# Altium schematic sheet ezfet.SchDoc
size 431 x 279 mm; Date: Not shown in title block; ApprovedBy: Not shown in title block; CheckedBy: Not shown in title block; Author: Not shown in title block; CompanyName: Not shown in title block; Engineer: Not shown in title block; Organization: Not shown in title block; Address1: Not shown in title block; Address2: Not shown in title block; Address3: Not shown in title block; Address4: Not shown in title block; DocumentNumber: 1; Revision: Use project parameter SCH_Rev; SheetNumber: 1; SheetTotal: 6; PageSetup: Record=PageOptions¦CenterHorizontal=True¦CenterVertical=True¦PrintScale=1.00¦XCorrection=1.00¦YCorrection=1.00¦PrintKind=0¦BorderSize=5000000¦LeftOffset=0¦BottomOffset=0¦Orientation=2¦PaperLength=1000¦PaperWidth=1000¦Scale=100¦PaperSource=15¦PrintQuality=600¦MediaType=1¦DitherType=10¦PaperKind=Letter¦PrintScaleMode=1
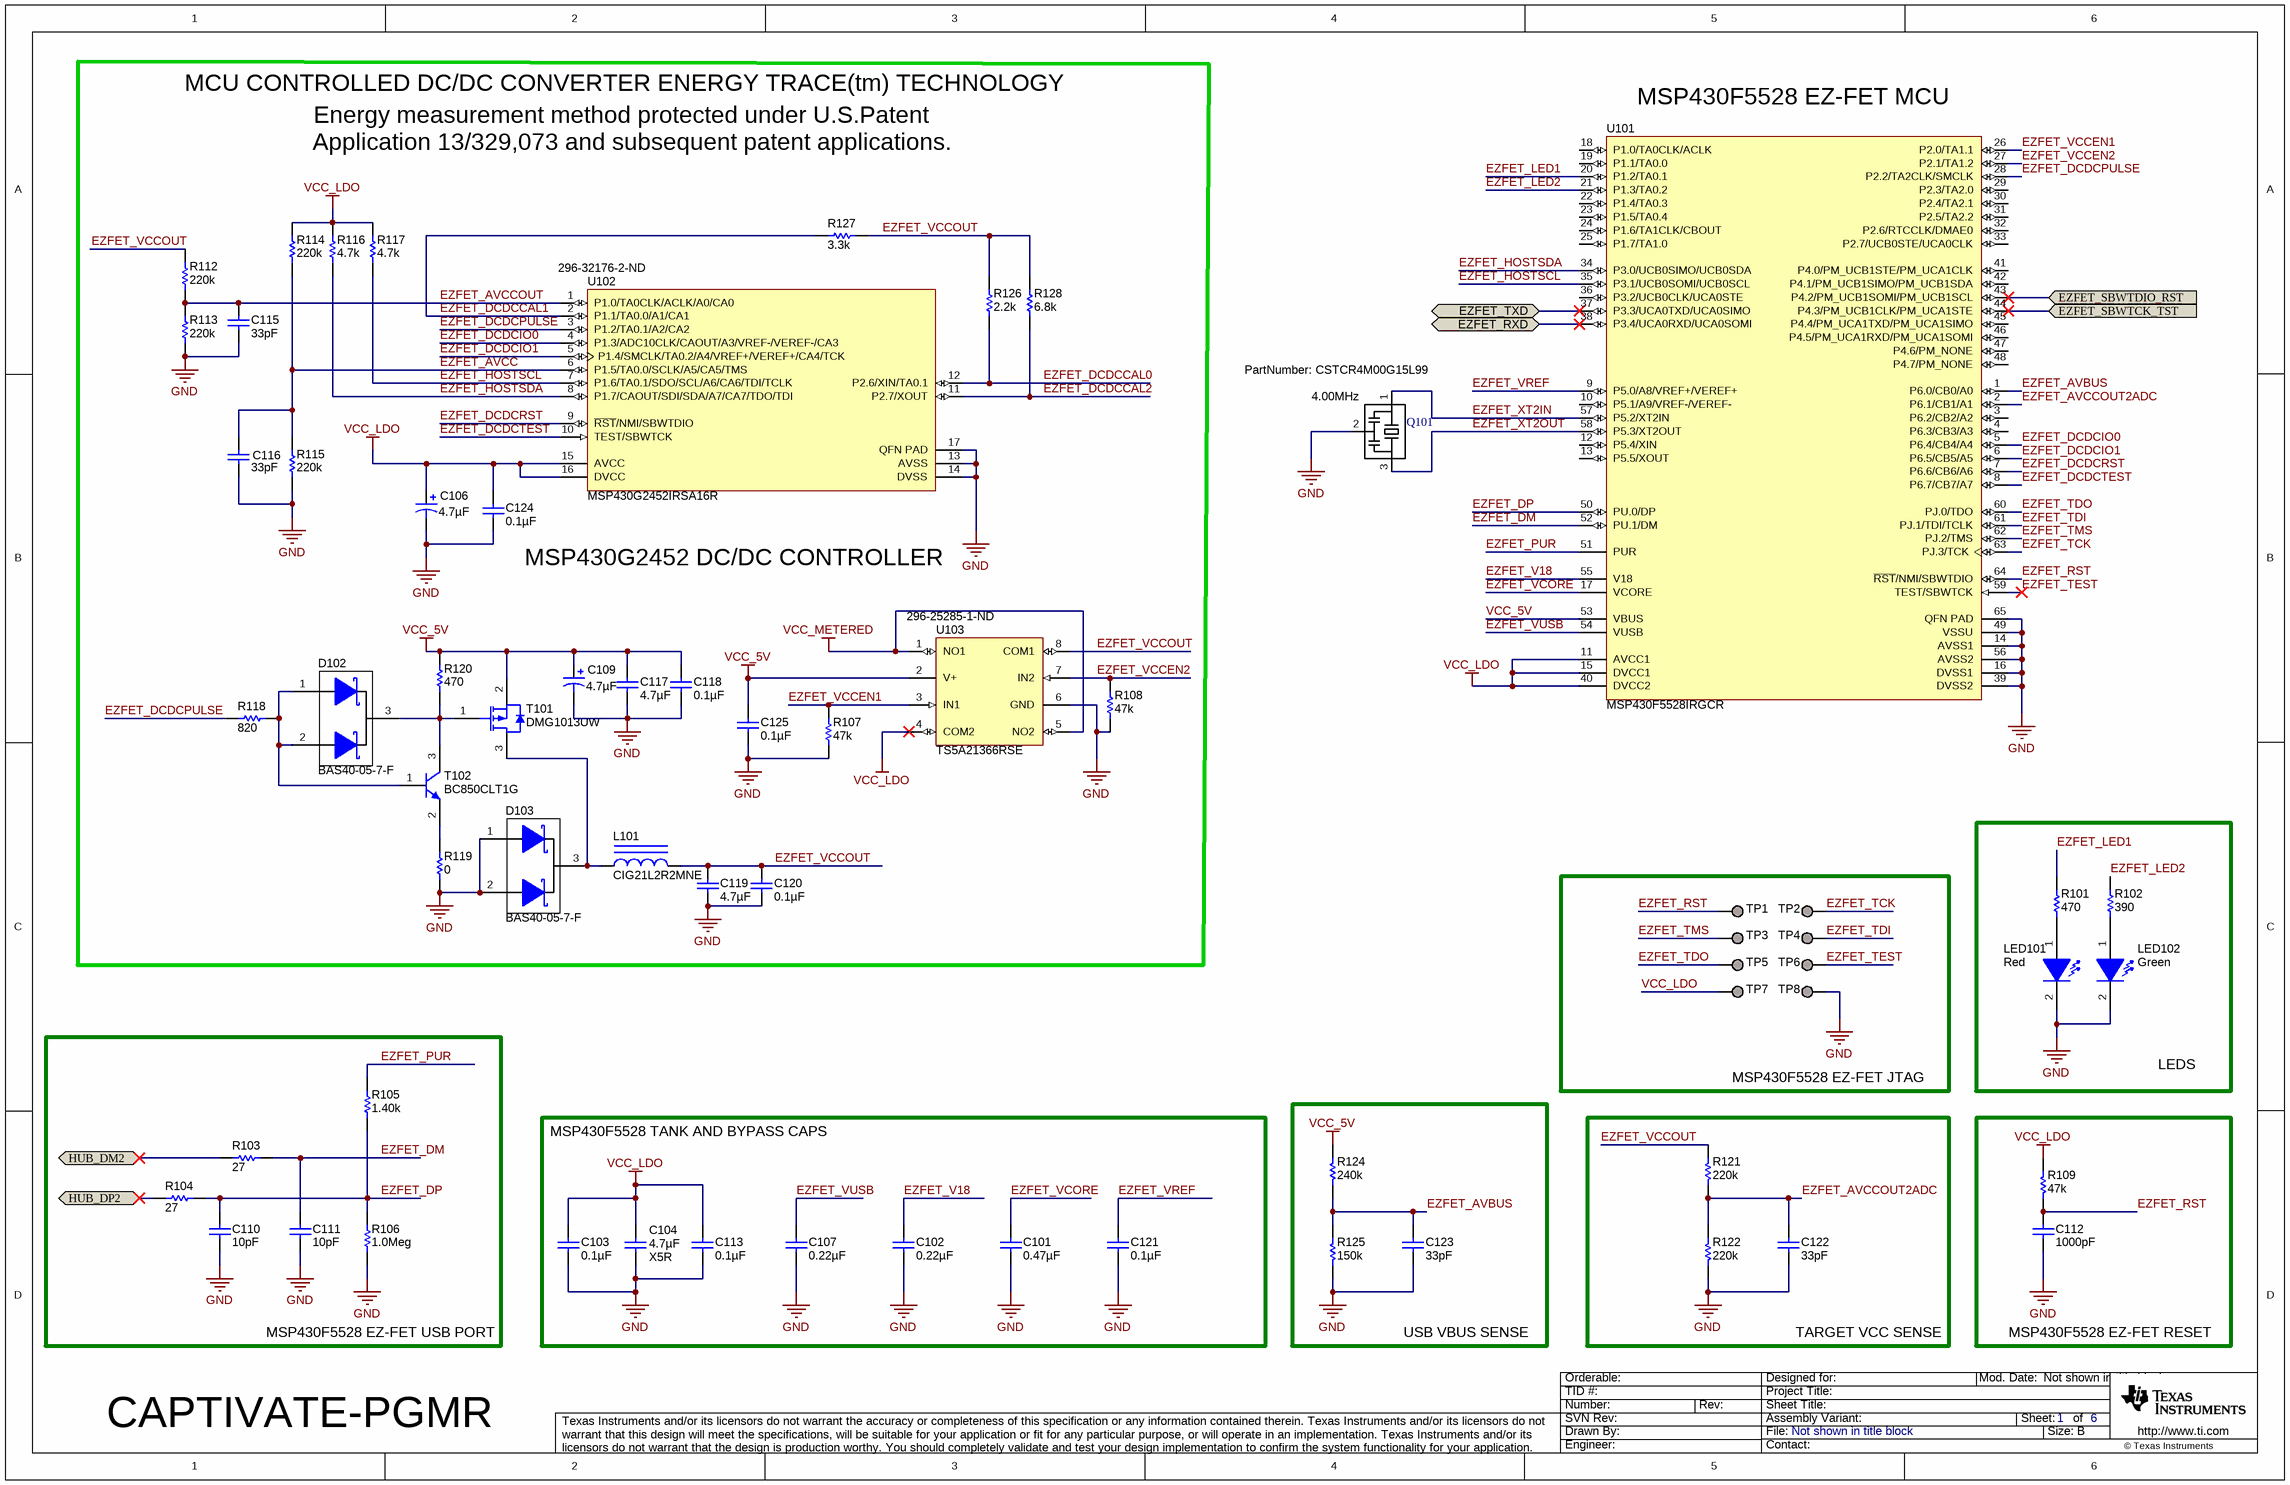
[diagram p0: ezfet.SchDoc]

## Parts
C101  ValueDisplayed: 0.47µF  [0402]  (hidden comment: GRM155R61A474KE15D)
C102  ValueDisplayed: 0.22µF  [0402]  (hidden comment: GRM155R61A224KE19D)
C103  ValueDisplayed: 0.1µF  [0402]  (hidden comment: C1005X5R1A104K)
C104  ValueDisplayed: 4.7µF  TempCo: X5R  [0603]  (hidden comment: CGB3B1X5R1A475K055AC)
C106  ValueDisplayed: 4.7µF  [3216-18]  (hidden comment: 293D475X9010A2TE3)
C107  ValueDisplayed: 0.22µF  [0402]  (hidden comment: GRM155R61A224KE19D)
C109  ValueDisplayed: 4.7µF  [3216-18]  (hidden comment: 293D475X9010A2TE3)
C110  ValueDisplayed: 10pF  [0402]  (hidden comment: 500R07S100JV4T)
C111  ValueDisplayed: 10pF  [0402]  (hidden comment: 500R07S100JV4T)
C112  ValueDisplayed: 1000pF  [0402]  (hidden comment: C1005X7R1H102K)
C113  ValueDisplayed: 0.1µF  [0402]  (hidden comment: C1005X5R1A104K)
C115  ValueDisplayed: 33pF  [0402]  (hidden comment: GRM1555C1H330JA01D)
C116  ValueDisplayed: 33pF  [0402]  (hidden comment: GRM1555C1H330JA01D)
C117  ValueDisplayed: 4.7µF  [0603]  (hidden comment: 0603ZD475KAT2A)
C118  ValueDisplayed: 0.1µF  [0402]  (hidden comment: C1005X5R1A104K)
C119  ValueDisplayed: 4.7µF  [0603]  (hidden comment: 0603ZD475KAT2A)
C120  ValueDisplayed: 0.1µF  [0402]  (hidden comment: C1005X5R1A104K)
C121  ValueDisplayed: 0.1µF  [0402]  (hidden comment: C1005X5R1A104K)
C122  ValueDisplayed: 33pF  [0402]  (hidden comment: GRM1555C1H330JA01D)
C123  ValueDisplayed: 33pF  [0402]  (hidden comment: GRM1555C1H330JA01D)
C124  ValueDisplayed: 0.1µF  [0402]  (hidden comment: C1005X5R1A104K)
C125  ValueDisplayed: 0.1µF  [0402]  (hidden comment: C1005X5R1A104K)
D102  BAS40-05-7-F  [SOT-23]
D103  BAS40-05-7-F  [SOT-23]
L101  CIG21L2R2MNE  [0805_HV]
LED101  value Red  [LED_LTST-C190_Red]  (hidden comment: LTST-C190CKT)
LED102  value Green  [LED_LTST-C190]  (hidden comment: LTST-C190GKT)
Q101  Value Displayed: 4.00MHz  PartNumber: CSTCR4M00G15L99  [CSTCR CERAMIC RESONATOR - MURATA]  (hidden comment: MURATA-FILTER_CSTCR4M00G15)
R101  value 470  [0402]  (hidden comment: CRCW0402470RJNED)
R102  value 390  [0402]  (hidden comment: CRCW0402390RJNED)
R103  value 27  [0402]  (hidden comment: CRCW040227R0JNED)
R104  value 27  [0402]  (hidden comment: CRCW040227R0JNED)
R105  ValueDisplayed: 1.40k  [0402]  (hidden comment: CRCW04021K40FKED)
R106  value 1.0Meg  [0402]  (hidden comment: CRCW04021M00JNED)
R107  ValueDisplayed: 47k  [0402]  (hidden comment: CRCW040247K0JNED)
R108  ValueDisplayed: 47k  [0402]  (hidden comment: CRCW040247K0JNED)
R109  value 47k  [0402]  (hidden comment: CRCW040247K0JNED)
R112  ValueDisplayed: 220k  [0402]  (hidden comment: CRCW0402220KJNED)
R113  ValueDisplayed: 220k  [0402]  (hidden comment: CRCW0402220KJNED)
R114  ValueDisplayed: 220k  [0402]  (hidden comment: CRCW0402220KJNED)
R115  ValueDisplayed: 220k  [0402]  (hidden comment: CRCW0402220KJNED)
R116  ValueDisplayed: 4.7k  [0402]  (hidden comment: CRCW04024K70JNED)
R117  ValueDisplayed: 4.7k  [0402]  (hidden comment: CRCW04024K70JNED)
R118  ValueDisplayed: 820  [0402]  (hidden comment: CRCW0402820RJNED)
R119  ValueDisplayed: 0  [0402]  (hidden comment: CRCW04020000Z0ED)
R120  ValueDisplayed: 470  [0402]  (hidden comment: CRCW0402470RJNED)
R121  value 220k  [0402]  (hidden comment: CRCW0402220KJNED)
R122  value 220k  [0402]  (hidden comment: CRCW0402220KJNED)
R124  value 240k  [0402]  (hidden comment: CRCW0402240KJNED)
R125  value 150k  [0402]  (hidden comment: CRCW0402150KFKED)
R126  ValueDisplayed: 2.2k  [0402]  (hidden comment: CRCW04022K20JNED)
R127  ValueDisplayed: 3.3k  [0402]  (hidden comment: CRCW04023K30JNED)
R128  ValueDisplayed: 6.8k  [0402]  (hidden comment: CRCW04026K80JNED)
T101  DMG1013UW  [SOT-323]
T102  BC850CLT1G  [SOT-23]
TP1  TESTPOINT  [TP_VIA_060RND040]  (value not drawn)  (no BOM)
TP2  TESTPOINT  [TP_VIA_060RND040]  (value not drawn)  (no BOM)
TP3  TESTPOINT  [TP_VIA_060RND040]  (value not drawn)  (no BOM)
TP4  TESTPOINT  [TP_VIA_060RND040]  (value not drawn)  (no BOM)
TP5  TESTPOINT  [TP_VIA_060RND040]  (value not drawn)  (no BOM)
TP6  TESTPOINT  [TP_VIA_060RND040]  (value not drawn)  (no BOM)
TP7  TESTPOINT  [TP_VIA_060RND040]  (value not drawn)  (no BOM)
TP8  TESTPOINT  [TP_VIA_060RND040]  (value not drawn)  (no BOM)
U101  MSP430F5528IRGCR  [RGC0064B]
U102  MSP430G2452IRSA16R  Supplier Part Number 1: 296-32176-2-ND  [RSA0016B]
U103  TS5A21366RSE  Supplier Part Number 1: 296-25285-1-ND  [RSE0008A]

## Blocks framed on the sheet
LEDS: LED101 LED102 R101 R102
MSP430F5528 EZ-FET JTAG: TP1-TP8
MSP430F5528 EZ-FET USB PORT: C110 C111 R103-R106
MSP430F5528 TANK AND BYPASS CAPS: C101-C104 C107 C113 C121
USB VBUS SENSE: C123 R124 R125
TARGET VCC SENSE: C122 R121 R122
MSP430F5528 EZ-FET RESET: C112 R109

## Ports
EZFET_RXD (bidir), EZFET_SBWTCK_TST, EZFET_SBWTDIO_RST, EZFET_TXD (bidir), HUB_DM2 (bidir), HUB_DP2 (bidir)

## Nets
GND: C101.2 C102.2 C103.2 C104.2 C106.2(-) C107.2 C109.2(-) C110.2 C111.2 C112.2 C113.2 C115.2 C116.2 C117.2 C118.2 C119.2 C120.2 C121.2 C122.2 C123.2 C124.2 C125.2 D103.1(A) D103.2(K) LED101.2(K) LED102.2(K) Q101.2 R106.2 R107.1 R108.1 R113.1 R115.1 R119.2 R122.1 R125.1 TP8.1 U101.14(AVSS1) U101.16(DVSS1) U101.39(DVSS2) U101.49(VSSU) U101.56(AVSS2) U101.65(QFN_PAD) U102.13(AVSS) U102.14(DVSS) U102.17(QFN_PAD) U103.6(GND)
VCC_5V: C109.1(+) C117.1 C118.1 C125.1 R120.1 R124.2 T101.2(S) U101.53(VBUS) U103.2(V+)
VCC_LDO: C103.1 C104.1 C106.1(+) C113.1 C124.1 R109.2 R114.2 R116.2 R117.2 TP7.1 U101.11(AVCC1) U101.15(DVCC1) U101.40(DVCC2) U102.15(AVCC) U102.16(DVCC) U103.4(COM2)
VCC_METERED: U103.1(NO1) U103.5(NO2)
EZFET_AVBUS: C123.1 R124.1 R125.2 U101.1(P6.0/CB0/A0)
EZFET_AVCC: C116.1 R114.1 R115.2 U102.6(P1.5/TA0.0/SCLK/A5/CA5/TMS)
EZFET_AVCCOUT: C115.1 R112.1 R113.2 U102.1(P1.0/TA0CLK/ACLK/A0/CA0)
EZFET_AVCCOUT2ADC: C122.1 R121.1 R122.2 U101.2(P6.1/CB1/A1)
EZFET_DCDCCAL0: R126.1 U102.12(P2.6/XIN/TA0.1)
EZFET_DCDCCAL1: R127.1 U102.2(P1.1/TA0.0/A1/CA1)
EZFET_DCDCCAL2: R128.1 U102.11(P2.7/XOUT)
EZFET_DCDCIO0: U101.5(P6.4/CB4/A4) U102.4(P1.3/ADC10CLK/CAOUT/A3/VREF-/VEREF-/CA3)
EZFET_DCDCIO1: U101.6(P6.5/CB5/A5) U102.5(P1.4/SMCLK/TA0.2/A4/VREF+/VEREF+/CA4/TCK)
EZFET_DCDCPULSE: R118.2 U101.28(P2.2/TA2CLK/SMCLK) U102.3(P1.2/TA0.1/A2/CA2)
EZFET_DCDCRST: U101.7(P6.6/CB6/A6) U102.9(~{RST}/NMI/SBWTDIO)
EZFET_DCDCTEST: U101.8(P6.7/CB7/A7) U102.10(TEST/SBWTCK)
EZFET_DM: C111.1 R103.2 U101.52(PU.1/DM)
EZFET_DP: C110.1 R104.2 R105.2 R106.1 U101.50(PU.0/DP)
EZFET_HOSTSCL: R117.1 U101.35(P3.1/UCB0SOMI/UCB0SCL) U102.7(P1.6/TA0.1/SDO/SCL/A6/CA6/TDI/TCLK)
EZFET_HOSTSDA: R116.1 U101.34(P3.0/UCB0SIMO/UCB0SDA) U102.8(P1.7/CAOUT/SDI/SDA/A7/CA7/TDO/TDI)
EZFET_LED1: R101.2 U101.20(P1.2/TA0.1)
EZFET_LED2: R102.2 U101.21(P1.3/TA0.2)
EZFET_PUR: R105.1 U101.51(PUR)
EZFET_RST: C112.1 R109.1 TP1.1 U101.64(~{RST}/NMI/SBWTDIO)
EZFET_RXD: U101.38(P3.4/UCA0RXD/UCA0SOMI) ; port EZFET_RXD
EZFET_SBWTCK_TST: U101.44(P4.3/PM_UCB1CLK/PM_UCA1STE) ; port EZFET_SBWTCK_TST
EZFET_SBWTDIO_RST: U101.43(P4.2/PM_UCB1SOMI/PM_UCB1SCL) ; port EZFET_SBWTDIO_RST
EZFET_TCK: TP2.1 U101.63(PJ.3/TCK)
EZFET_TDI: TP4.1 U101.61(PJ.1/TDI/TCLK)
EZFET_TDO: TP5.1 U101.60(PJ.0/TDO)
EZFET_TEST: TP6.1 U101.59(TEST/SBWTCK)
EZFET_TMS: TP3.1 U101.62(PJ.2/TMS)
EZFET_TXD: U101.37(P3.3/UCA0TXD/UCA0SIMO) ; port EZFET_TXD
EZFET_V18: C102.1 U101.55(V18)
EZFET_VCCEN1: R107.2 U101.26(P2.0/TA1.1) U103.3(IN1)
EZFET_VCCEN2: R108.2 U101.27(P2.1/TA1.2) U103.7(IN2)
EZFET_VCCOUT: C119.1 C120.1 L101.2 R112.2 R121.2 R126.2 R127.2 R128.2 U103.8(COM1)
EZFET_VCORE: C101.1 U101.17(VCORE)
EZFET_VREF: C121.1 U101.9(P5.0/A8/VREF+/VEREF+)
EZFET_VUSB: C107.1 U101.54(VUSB)
EZFET_XT2IN: Q101.1 U101.57(P5.2/XT2IN)
EZFET_XT2OUT: Q101.3 U101.58(P5.3/XT2OUT)
HUB_DM2: R103.1 ; port HUB_DM2
HUB_DP2: R104.1 ; port HUB_DP2
NetD102_1: D102.1(A) D102.2(K) R118.1 T102.1(B)
NetD102_3: D102.3(A) R120.2 T101.1(G) T102.3(C)
NetD103_3: D103.3(A) L101.1 T101.3(D)
NetLED101_1: LED101.1(A) R101.1
NetLED102_1: LED102.1(A) R102.1
NetR119_1: R119.1 T102.2(E)

Not connected (* = marked no-connect by the designer): U101 3(P6.2/CB2/A2) 4(P6.3/CB3/A3) 10(P5.1/A9/VREF-/VEREF-) 12(P5.4/XIN) 13(P5.5/XOUT) 18(P1.0/TA0CLK/ACLK) 19(P1.1/TA0.0) 22(P1.4/TA0.3) 23(P1.5/TA0.4) 24(P1.6/TA1CLK/CBOUT) 25(P1.7/TA1.0) 29(P2.3/TA2.0) 30(P2.4/TA2.1) 31(P2.5/TA2.2) 32(P2.6/RTCCLK/DMAE0) 33(P2.7/UCB0STE/UCA0CLK) 36(P3.2/UCB0CLK/UCA0STE) 41(P4.0/PM_UCB1STE/PM_UCA1CLK) 42(P4.1/PM_UCB1SIMO/PM_UCB1SDA) 45(P4.4/PM_UCA1TXD/PM_UCA1SIMO) 46(P4.5/PM_UCA1RXD/PM_UCA1SOMI) 47(P4.6/PM_NONE) 48(P4.7/PM_NONE)

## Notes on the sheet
- MCU CONTROLLED DC/DC CONVERTER ENERGY TRACE(tm) TECHNOLOGY
- (near U101) MSP430F5528 EZ-FET MCU
- Energy measurement method protected under U.S.Patent
- Application 13/329,073 and subsequent patent applications.
- MSP430G2452 DC/DC CONTROLLER
- CAPTIVATE-PGMR

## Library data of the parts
C101 = GRM155R61A474KE15D: CAP, CERM, 0.47uF, 10V, +/-10%, X5R, 0402; Manufacturer: MuRata; Polarized: N; CompType: Capacitor; U/M: EA; Cap_F: 0.00000047; Tolerance_%: 10; Value1: Unknown; TaMin_C: -55; TaMax_C: 85
C102 C107 = GRM155R61A224KE19D: CAP, CERM, 0.22uF, 10V, +/-10%, X5R, 0402; Manufacturer: MuRata; Polarized: N; CompType: Capacitor; U/M: EA; Cap_F: 0.00000022; Tolerance_%: 10; Value1: Unknown; TaMin_C: -55; TaMax_C: 85
C103 C113 C118 C120 C121 C125 = C1005X5R1A104K: CAP, CERM, 0.1uF, 10V, +/-10%, X5R, 0402; Manufacturer: TDK; Polarized: N; CompType: Capacitor; U/M: EA; Cap_F: 0.0000001; Tolerance_%: 10; ESR_Ohm: 0.0186; Value1: 0.0186 ohm; TaMin_C: -55; TaMax_C: 85
C104 = CGB3B1X5R1A475K055AC: CAP, CERM, 4.7 µF, 10 V, +/- 10%, X5R, 0603; Manufacturer: TDK; Polarized: N; CompType: Capacitor; Value: 4.7uF; U/M: EA; Cap_F: 0.0000047; Tolerance_%: 10; Value1: Unknown; VDC_V: 10V; TaMin_C: -55; TaMax_C: 85
C106 C109 = 293D475X9010A2TE3: CAP, TA, 4.7 µF, 10 V, +/- 10%, 5 ohm, SMD; Manufacturer: Vishay-Sprague; Polarized: Y; CompType: Capacitor; Value: 4.7uF; U/M: EA; Cap_F: 0.0000047; Tolerance_%: 10; Value1: 5 ohm; Value2: 10V; ESR_ohm: 5; IRMS_A: 0.12; TaMin_C: -55; TaMax_C: 125; Cap_Case: A
C110 C111 = 500R07S100JV4T: CAP, CERM, 10pF, 50V, +/-5%, C0G/NP0, 0402; Manufacturer: Johanson Technology; Polarized: N; CompType: Capacitor; U/M: EA; Cap_F: 0.00000000001; Tolerance_%: 5; Value1: Unknown; VDC_V: 50; TaMin_C: -55; TaMax_C: 125
C112 = C1005X7R1H102K: CAP, CERM, 1000pF, 50V, +/-10%, X7R, 0402; Manufacturer: TDK; Polarized: N; CompType: Capacitor; U/M: EA; Cap_F: 0.000000001; Tolerance_%: 10; ESR_Ohm: 0.2381; Value1: 0.2381 ohm; VDC_V: 50; TaMin_C: -55; TaMax_C: 125
C115 C116 C122 C123 = GRM1555C1H330JA01D: CAP, CERM, 33pF, 50V, +/-5%, C0G/NP0, 0402; Manufacturer: MuRata; Polarized: N; CompType: Capacitor; U/M: EA; Cap_F: 0.000000000033; Tolerance_%: 5; Value1: Unknown; VDC_V: 50; TaMin_C: -55; TaMax_C: 125
C117 C119 = 0603ZD475KAT2A: CAP, CERM, 4.7 µF, 10 V, +/- 10%, X5R, 0603; Manufacturer: AVX; Polarized: N; CompType: Capacitor; Value: 4.7uF; U/M: EA; Cap_F: 0.0000047; Tolerance_%: 10; Value1: Unknown; Value2: 10V; TaMin_C: -55; TaMax_C: 85
C124 = C1005X5R1A104K: CAP, CERM, 0.1 µF, 10 V, +/- 10%, X5R, 0402; Manufacturer: TDK; Polarized: N; CompType: Capacitor; Value: 0.1uF; U/M: EA; Cap_F: 0.0000001; Tolerance_%: 10; ESR_ohm: 0.0186; Value1: 0.0186 ohm; Value2: 10V; TaMin_C: -55; TaMax_C: 85
D102 D103 = BAS40-05-7-F: Diode, Schottky, 40V, 0.2A, SOT-23; Manufacturer: Diodes Inc.; SymbolCreator: a0412235; U/M: EA; Vf_V: 0.9; Value2: 0.9V; Io_A: 0.2; Vr_V: 40
L101 = CIG21L2R2MNE: Inductor, Shielded, Composite, 2.2uH, 0.95A, 0.16 ohm, SMD; Manufacturer: Samsung; Ind_H: 2.2E-6; ValueDisplayed: 2.2µH; Imax_A: 0.95; Irms: 0.95A @ 40C rise; DCR_ohm: 0.16
LED101 = LTST-C190CKT: LED, Red, SMD; Manufacturer: Lite-On; Vf_V: 2; Value2: 2V; Io_A: 0.02; Tjmax_C: 85; Power_TotalModule: 0.0625; Value1: 0.0625W; U/M: EA
LED102 = LTST-C190GKT: LED, Green, SMD; Manufacturer: Lite-On; Vf_V: 2.1; Value2: 2.1V; Io_A: 0.02; Power_TotalModule: 0.1; Value1: 0.1W; U/M: EA
Q101 = MURATA-FILTER_CSTCR4M00G15: 4.00MHz resonator
R101 = CRCW0402470RJNED: RES, 470 ohm, 5%, 0.063W, 0402; Manufacturer: Vishay-Dale; CompType: Resistor; Value_Code: 470R; Tolerance_%: 5; Power_W: 0.063; VDC_V: 50; TempCo: 200 ppm/C; EIA_Code: E24; U/M: EA
R102 = CRCW0402390RJNED: RES, 390 ohm, 5%, 0.063W, 0402; Manufacturer: Vishay-Dale; CompType: Resistor; Value_Code: 390R; Tolerance_%: 5; Power_W: 0.063; VDC_V: 50; TempCo: 200 ppm/C; EIA_Code: E24; U/M: EA
R103 R104 = CRCW040227R0JNED: RES, 27 ohm, 5%, 0.063W, 0402; Manufacturer: Vishay-Dale; CompType: Resistor; Value_Code: 27R0; Tolerance_%: 5; Power_W: 0.063; VDC_V: 50; TempCo: 200 ppm/C; EIA_Code: E24; U/M: EA
R105 = CRCW04021K40FKED: RES, 1.40 k, 1%, 0.063 W, 0402; Manufacturer: Vishay-Dale; CompType: Resistor; Res_ohm: 1400; Value_Code: 1k40; Tolerance_%: 1; Power_W: 0.063; Value2: 0.063W; VDC_V: 50; TempCo: 100 ppm/C; EIA_Code: E96; U/M: EA; Value: 1.40k
R106 = CRCW04021M00JNED: RES, 1.0Meg ohm, 5%, 0.063W, 0402; Manufacturer: Vishay-Dale; CompType: Resistor; Res_ohm: 1000000; Value_Code: 1M00; Tolerance_%: 5; Power_W: 0.063; VDC_V: 50; TempCo: 200 ppm/C; EIA_Code: E24; U/M: EA
R107 R108 = CRCW040247K0JNED: RES, 47 k, 5%, 0.063 W, 0402; Manufacturer: Vishay-Dale; CompType: Resistor; Res_ohm: 47000; Value_Code: 47k0; Tolerance_%: 5; Power_W: 0.063; Value2: 0.063W; VDC_V: 50; TempCo: 200 ppm/C; EIA_Code: E24; U/M: EA; Value: 47k
R109 = CRCW040247K0JNED: RES, 47k ohm, 5%, 0.063W, 0402; Manufacturer: Vishay-Dale; CompType: Resistor; Res_ohm: 47000; Value_Code: 47k0; Tolerance_%: 5; Power_W: 0.063; VDC_V: 50; TempCo: 200 ppm/C; EIA_Code: E24; U/M: EA
R112-R115 = CRCW0402220KJNED: RES, 220 k, 5%, 0.063 W, 0402; Manufacturer: Vishay-Dale; CompType: Resistor; Value: 220k; Res_ohm: 220000; Tolerance_%: 5; Power_W: 0.063; Value2: 0.063W; VDC_V: 50; TempCo: 200 ppm/C; EIA_Code: E24; U/M: EA
R116 R117 = CRCW04024K70JNED: RES, 4.7 k, 5%, 0.063 W, 0402; Manufacturer: Vishay-Dale; CompType: Resistor; Value: 4.7k; Res_ohm: 4700; Value_Code: 4k70; Tolerance_%: 5; Power_W: 0.063; Value2: 0.063W; VDC_V: 50; TempCo: 200 ppm/C; EIA_Code: E24; U/M: EA
R118 = CRCW0402820RJNED: RES, 820, 5%, 0.063 W, 0402; Manufacturer: Vishay-Dale; CompType: Resistor; Value_Code: 820R; Tolerance_%: 5; Power_W: 0.063; Value2: 0.063W; VDC_V: 50; TempCo: 200 ppm/C; EIA_Code: E24; U/M: EA; Value: 820
R119 = CRCW04020000Z0ED: RES, 0, 5%, 0.063 W, 0402; Manufacturer: Vishay-Dale; CompType: Resistor; Value_Code: 0000; Tolerance_%: 5; Power_W: 0.063; Value2: 0.063W; VDC_V: 50; TempCo: 200 ppm/C; EIA_Code: E24; U/M: EA; Value: 0
R120 = CRCW0402470RJNED: RES, 470, 5%, 0.063 W, 0402; Manufacturer: Vishay-Dale; CompType: Resistor; Value_Code: 470R; Tolerance_%: 5; Power_W: 0.063; Value2: 0.063W; VDC_V: 50; TempCo: 200 ppm/C; EIA_Code: E24; U/M: EA; Value: 470
R121 R122 = CRCW0402220KJNED: RES, 220k ohm, 5%, 0.063W, 0402; Manufacturer: Vishay-Dale; CompType: Resistor; Res_ohm: 220000; Tolerance_%: 5; Power_W: 0.063; VDC_V: 50; TempCo: 200 ppm/C; EIA_Code: E24; U/M: EA
R124 = CRCW0402240KJNED: RES, 240k ohm, 5%, 0.063W, 0402; Manufacturer: Vishay-Dale; CompType: Resistor; Res_ohm: 240000; Tolerance_%: 5; Power_W: 0.063; VDC_V: 50; TempCo: 200 ppm/C; EIA_Code: E24; U/M: EA
R125 = CRCW0402150KFKED: RES, 150k ohm, 1%, 0.063W, 0402; Manufacturer: Vishay-Dale; CompType: Resistor; Res_ohm: 150000; Tolerance_%: 1; Power_W: 0.063; VDC_V: 50; TempCo: 100 ppm/C; EIA_Code: E96; U/M: EA
R126 = CRCW04022K20JNED: RES, 2.2 k, 5%, 0.063 W, 0402; Manufacturer: Vishay-Dale; CompType: Resistor; Value: 2.2k; Res_ohm: 2200; Value_Code: 2k20; Tolerance_%: 5; Power_W: 0.063; Value2: 0.063W; VDC_V: 50; TempCo: 200 ppm/C; EIA_Code: E24; U/M: EA
R127 = CRCW04023K30JNED: RES, 3.3 k, 5%, 0.063 W, 0402; Manufacturer: Vishay-Dale; CompType: Resistor; Value: 3.3k; Res_ohm: 3300; Value_Code: 3k30; Tolerance_%: 5; Power_W: 0.063; Value2: 0.063W; VDC_V: 50; TempCo: 200 ppm/C; EIA_Code: E24; U/M: EA
R128 = CRCW04026K80JNED: RES, 6.8 k, 5%, 0.063 W, 0402; Manufacturer: Vishay-Dale; CompType: Resistor; Value: 6.8k; Res_ohm: 6800; Value_Code: 6k80; Tolerance_%: 5; Power_W: 0.063; Value2: 0.063W; VDC_V: 50; TempCo: 200 ppm/C; EIA_Code: E24; U/M: EA
T101 = BSS84W-7-F: MOSFET, P-CH, -50V, -0.13A, SOT-323; Manufacturer: Diodes Inc.; Alternate Manufacturer: None; U/M: EA; ChType: P; VdsMax_V: -50; Value1: 10 ohm; Rdson45_Ohm: 10; Value2: ? nC; Vgs_V: -20; IdsMax_A: -0.13
T102 = BC850CLT1G, ON Semiconductor: Transistor, NPN, 45V, 0.1A, SOT-23; CompType: BJT; PNP: 0; NPN: 1; Vceo_V: 45; Vcesat1_V: 0.7; Value: 0.7V; IcRated_A: 0.1; HfeMax: 800; TaMin_C: -55; TaMax_C: 150; U/M: EA
TP1-TP8 = TESTPOINT: TEST POINT.  No entry in BOM.
U101 = MSP430F5528IRGCR: 25 MHz Mixed Signal Microcontroller with 128 KB Flash, 8192 B SRAM and 47 GPIOs, -40 to 85 degC, 64-pin QFN (RGC), Green (RoHS & no Sb/Br); Manufacturer: Texas Instruments; ADC: 12-bit SAR; ADC Channels: 16; Brown Out Reset: Yes; DMA: 3; Flash(KB): 128; Frequency(MHz): 25; GPIO: 47; Multiplier: 32x32; SRAM(B): 8192; SubFamily: 5 Series; Timers - 16-bit: 4; USB: 1; USCI_A (UART/LIN/IrDA/SPI): 2
U102 = MSP430G2452IRSA16R: 16 MHz Mixed Signal Microcontroller with 8 KB Flash, 256 B SRAM and 16 GPIOs, 16-pin QFN (RSA), Green (RoHS & no Sb/Br); Alternate Manufacturer: Texas Instruments; Alternate PartNumber: Equivalent; ADC: 10-bit SAR; ADC Channels: 8; Brown Out Reset: Yes; Frequency(MHz): 16; Pin/Package: 14TSSOP, 16QFN, 20PDIP, 20TSSOP; SRAM(B): 256; SubFamily: Value Line; Timers - 16-bit: 1; USI: (I2C/SPI)
U103 = TS5A21366RSE: 0.75-Ω DUAL SPST ANALOG SWITCH WITH 1.8-V COMPATIBLE INPUT LOGIC, RSE0008A; Manufacturer: Texas Instruments; SymbolCreator: a0272918; CompType: IC; U/M: EA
